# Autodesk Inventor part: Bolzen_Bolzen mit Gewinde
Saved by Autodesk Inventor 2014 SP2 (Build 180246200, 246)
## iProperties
Created: 2015-07
Part Number: Bolzen_Bolzen mit Gewinde
Material: Generisch
Document SubType Name: Modeling
Designer: e_krauts
Density: 1 g/cm^3
Appearance: Vorgabe
Mass: 9.49442 g
Surface Area: 30.1123 cm^2
Volume: 9.49442 cm^3
Sending System: SolidWorks 2011
Last Author: e_boekem
Erstellt durch: XYZ
Werkstoff: AlCu4PbMg
Einheit: Stck.
UNIT_OF_MEASURE: Sachnummer
Author: e_krauts
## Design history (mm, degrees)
node "Bolzen_Bolzen mit Gewinde.ipt1"
node "M8 Gewindebohrung1"
node "Basis1"
